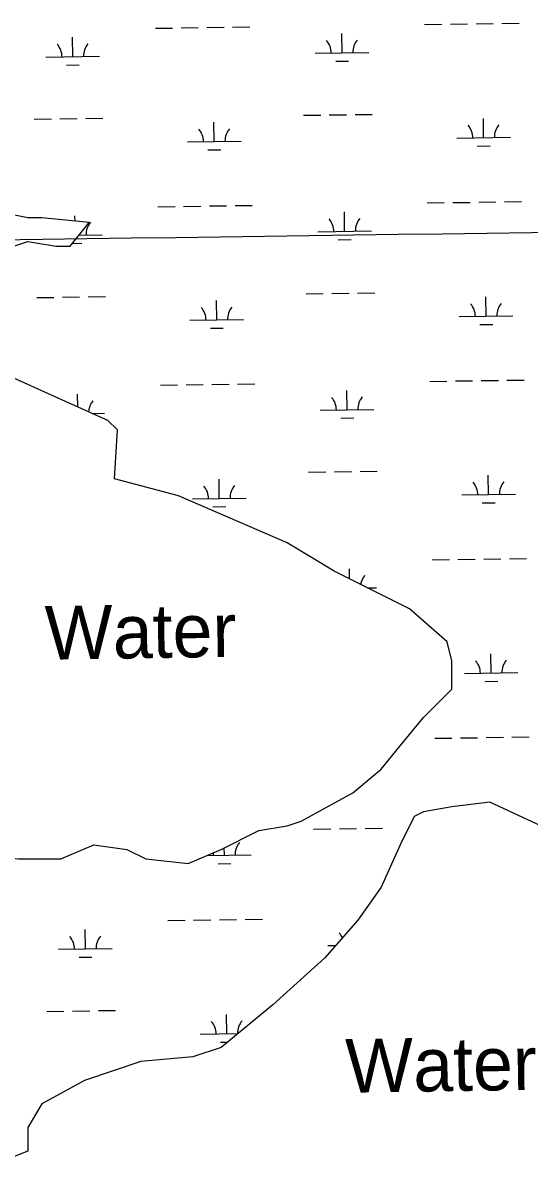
# Model space of a CAD drawing. Extents: x 3775218 to 3813389, y 343470 to 369318.
# Drawn here: x 3783560 to 3784504, y 353257 to 355414 of the extents above; entities that cross this region are included whole.
import ezdxf

# ---------------------------------------------------------------- set-up
doc = ezdxf.new("R2010")
doc.units = 0
for name, color, linetype in [('V-GRID-MAJR', 7, 'Continuous'), ('V-RIVR-IDEN', 7, 'Continuous'), ('V-TOPO-SHOR', 7, 'Continuous'), ('V-WETL-SWMP', 7, 'Continuous')]:
    doc.layers.add(name, color=color, linetype=linetype)

msp = doc.modelspace()

# ---------------------------------------------------------------- linework, layer by layer
at = {"layer": 'V-GRID-MAJR'}
msp.add_spline([(3779369.4, 354952.8), (3784672.7, 355025.7), (3789975.9, 355099.3), (3795279.1, 355173.8), (3800582.3, 355249), (3805885.5, 355325), (3811188.7, 355401.7)], degree=3, dxfattribs=at)
at = {"layer": 'V-TOPO-SHOR'}
for points in [[(3783542.1, 354998.2), (3783568.5, 355006.9), (3783621.1, 354998.2), (3783647.5, 354998.2), (3783682.6, 355042.1), (3783594.8, 355050.9), (3783568.5, 355050.9), (3783524.6, 355059.7)], [(3783730.2, 354564), (3783735.3, 354655.5), (3783717.7, 354673.1), (3783638.7, 354708.2), (3783542.1, 354752.1)], [(3784051.4, 353917.4), (3784077.7, 353926.2), (3784174.3, 353978.9), (3784227, 354022.8), (3784262.1, 354066.8), (3784306, 354119.5), (3784358.7, 354172.2), (3784358.7, 354224.9), (3784349.9, 354260.1), (3784279.7, 354321.6), (3784139.2, 354391.9), (3784051.4, 354444.6), (3783849.4, 354532.5), (3783730.2, 354564)], [(3783238.3, 354182.7), (3783243.6, 354172.2), (3783278.7, 354154.6), (3783252.4, 354075.5), (3783199.7, 354014), (3783199.7, 353970.1), (3783226, 353926.2), (3783287.5, 353908.6), (3783357.7, 353891), (3783410.4, 353864.7), (3783471.9, 353864.7), (3783550.9, 353855.9), (3783629.9, 353855.9), (3783691.4, 353882.2), (3783752.9, 353873.5), (3783788, 353855.9), (3783867, 353847.1), (3783928.5, 353873.5), (3783998.7, 353908.6), (3784051.4, 353917.4)], [(3784543.1, 353908.6), (3784429, 353961.3), (3784358.7, 353952.5), (3784306, 353943.7), (3784288.5, 353935), (3784262.1, 353882.2), (3784227, 353803.2), (3784183.1, 353741.7), (3784121.6, 353671.4), (3784025.1, 353583.5), (3783928.5, 353504.4), (3783875.8, 353486.8), (3783779.2, 353478.1), (3783673.8, 353442.9), (3783594.8, 353399), (3783568.5, 353355), (3783568.5, 353311.1)], [(3783568.5, 353311.1), (3783524.6, 353293.5), (3783463.1, 353293.5), (3783366.5, 353311.1), (3783322.6, 353267.2), (3783234.8, 353196.9)]]:
    msp.add_lwpolyline(points, dxfattribs=at)
at = {"layer": 'V-WETL-SWMP'}
for p, q in [((3783806, 355404.1), (3783838, 355404.5)), ((3783854, 355404.8), (3783886, 355405.2)), ((3783902, 355405.4), (3783934, 355405.9)), ((3783950, 355406.1), (3783982, 355406.6)), ((3784307.8, 355411.2), (3784339.8, 355411.6)), ((3784355.8, 355411.8), (3784387.8, 355412.3)), ((3784403.8, 355412.5), (3784435.8, 355413)), ((3784451.8, 355413.2), (3784483.8, 355413.6)), ((3783652.1, 355351.2), (3783651.6, 355387.2)), ((3784154, 355358.2), (3784153.5, 355394.2)), ((3783602.1, 355350.5), (3783702.1, 355351.9)), ((3784104, 355357.5), (3784204, 355358.9)), ((3784142.2, 355342.6), (3784166.2, 355343)), ((3783640.3, 355335.6), (3783664.3, 355335.9)), ((3783580.3, 355234.7), (3783612.3, 355235.2)), ((3783628.3, 355235.4), (3783660.3, 355235.8)), ((3783676.3, 355236.1), (3783708.3, 355236.5)), ((3784082.2, 355241.8), (3784114.2, 355242.2)), ((3784130.2, 355242.5), (3784162.2, 355242.9)), ((3784178.2, 355243.1), (3784210.2, 355243.6)), ((3784417.7, 355200.1), (3784417.2, 355236.1)), ((3783915.8, 355193), (3783915.3, 355229)), ((3783865.8, 355192.3), (3783965.8, 355193.7)), ((3784367.7, 355199.4), (3784467.7, 355200.8)), ((3783904, 355177.4), (3783928, 355177.7)), ((3784405.9, 355184.5), (3784429.9, 355184.8)), ((3784456.5, 355080.6), (3784488.5, 355081)), ((3783810.7, 355071.4), (3783842.7, 355071.9)), ((3783858.7, 355072.1), (3783890.7, 355072.6)), ((3783906.7, 355072.8), (3783938.7, 355073.2)), ((3783954.7, 355073.5), (3783986.7, 355073.9)), ((3784158.7, 355025.6), (3784158.2, 355061.6)), ((3784312.5, 355078.5), (3784344.5, 355079)), ((3784360.5, 355079.2), (3784392.5, 355079.6)), ((3784408.5, 355079.9), (3784440.5, 355080.3)), ((3783656.4, 355044.7), (3783656.3, 355054.5)), ((3783663.8, 355018.6), (3783706.8, 355019.2)), ((3784108.7, 355024.9), (3784208.7, 355026.3)), ((3783651.4, 355003), (3783669, 355003.3)), ((3784146.9, 355010), (3784170.9, 355010.3)), ((3784086.9, 354909.1), (3784118.9, 354909.6)), ((3784134.9, 354909.8), (3784166.9, 354910.3)), ((3784182.9, 354910.5), (3784214.9, 354911)), ((3783585, 354902.1), (3783617, 354902.5)), ((3783633, 354902.7), (3783665, 354903.2)), ((3783681, 354903.4), (3783713, 354903.9)), ((3783920.5, 354860.4), (3783920, 354896.4)), ((3784422.4, 354867.4), (3784421.9, 354903.4)), ((3784372.4, 354866.7), (3784472.4, 354868.1)), ((3783870.5, 354859.7), (3783970.5, 354861.1)), ((3783908.7, 354844.8), (3783932.7, 354845.1)), ((3784410.6, 354851.8), (3784434.6, 354852.2)), ((3783815.4, 354738.8), (3783847.4, 354739.2)), ((3783863.4, 354739.5), (3783895.4, 354739.9)), ((3783911.4, 354740.2), (3783943.4, 354740.6)), ((3783959.3, 354740.8), (3783991.3, 354741.3)), ((3784317.2, 354745.9), (3784349.2, 354746.3)), ((3784365.2, 354746.6), (3784397.2, 354747)), ((3784413.2, 354747.2), (3784445.2, 354747.7)), ((3784461.2, 354747.9), (3784493.2, 354748.4)), ((3783661.3, 354698.1), (3783661, 354721.9)), ((3784163.4, 354693), (3784162.9, 354729)), ((3784113.4, 354692.3), (3784213.4, 354693.7)), ((3783688, 354686.3), (3783711.5, 354686.6)), ((3784151.6, 354677.4), (3784175.6, 354677.7)), ((3783925.2, 354527.7), (3783924.7, 354563.7)), ((3784091.6, 354576.5), (3784123.6, 354577)), ((3784139.6, 354577.2), (3784171.6, 354577.6)), ((3784187.6, 354577.9), (3784219.6, 354578.3)), ((3784427.1, 354534.8), (3784426.5, 354570.8)), ((3783875.2, 354527), (3783975.2, 354528.4)), ((3784377.1, 354534.1), (3784477, 354535.5)), ((3783913.4, 354512.1), (3783937.4, 354512.5)), ((3784415.3, 354519.2), (3784439.3, 354519.5)), ((3784321.9, 354413.2), (3784353.9, 354413.7)), ((3784369.9, 354413.9), (3784401.9, 354414.4)), ((3784417.9, 354414.6), (3784449.9, 354415)), ((3784465.9, 354415.3), (3784497.9, 354415.7)), ((3784167.8, 354377.6), (3784167.5, 354396.3)), ((3784201.3, 354360.8), (3784218, 354361)), ((3784431.7, 354202.2), (3784431.2, 354238.2)), ((3784381.8, 354201.5), (3784481.7, 354202.9)), ((3784420, 354186.6), (3784444, 354186.9)), ((3784326.6, 354080.6), (3784358.6, 354081)), ((3784374.6, 354081.3), (3784406.6, 354081.7)), ((3784422.6, 354081.9), (3784454.6, 354082.4)), ((3784470.6, 354082.6), (3784502.6, 354083.1)), ((3784101, 353911.2), (3784133, 353911.7)), ((3784149, 353911.9), (3784181, 353912.3)), ((3784197, 353912.6), (3784229, 353913)), ((3783934.6, 353862.4), (3783934.4, 353876.4)), ((3783901.7, 353862), (3783984.6, 353863.1)), ((3783922.8, 353846.8), (3783946.8, 353847.2)), ((3783675.6, 353688), (3783675.1, 353724)), ((3783829.4, 353740.9), (3783861.4, 353741.3)), ((3783877.4, 353741.5), (3783909.4, 353742)), ((3783925.4, 353742.2), (3783957.4, 353742.7)), ((3783973.4, 353742.9), (3784005.4, 353743.4)), ((3783625.6, 353687.2), (3783725.6, 353688.7)), ((3784127.4, 353694.3), (3784141.9, 353694.5)), ((3783663.8, 353672.4), (3783687.8, 353672.7)), ((3783603.8, 353571.5), (3783635.8, 353571.9)), ((3783651.8, 353572.2), (3783683.8, 353572.6)), ((3783699.8, 353572.9), (3783731.8, 353573.3)), ((3783939.3, 353529.8), (3783938.8, 353565.8)), ((3783889.3, 353529.1), (3783959.8, 353530.1)), ((3783927.5, 353514.2), (3783940.6, 353514.4))]:
    msp.add_line(p, q, dxfattribs=at)
for points in [[(3783542.1, 354998.2), (3783568.5, 355006.9), (3783621.1, 354998.2), (3783647.5, 354998.2), (3783682.6, 355042.1), (3783594.8, 355050.9), (3783568.5, 355050.9), (3783524.6, 355059.7)], [(3783730.2, 354564), (3783735.3, 354655.5), (3783717.7, 354673.1), (3783638.7, 354708.2), (3783542.1, 354752.1)], [(3784051.4, 353917.4), (3784077.7, 353926.2), (3784174.3, 353978.9), (3784227, 354022.8), (3784262.1, 354066.8), (3784306, 354119.5), (3784358.7, 354172.2), (3784358.7, 354224.9), (3784349.9, 354260.1), (3784279.7, 354321.6), (3784139.2, 354391.9), (3784051.4, 354444.6), (3783849.4, 354532.5), (3783730.2, 354564)], [(3784543.1, 353908.6), (3784429, 353961.3), (3784358.7, 353952.5), (3784306, 353943.7), (3784288.5, 353935), (3784262.1, 353882.2), (3784227, 353803.2), (3784183.1, 353741.7), (3784121.6, 353671.4), (3784025.1, 353583.5), (3783928.5, 353504.4), (3783875.8, 353486.8), (3783779.2, 353478.1), (3783673.8, 353442.9), (3783594.8, 353399), (3783568.5, 353355), (3783568.5, 353311.1), (3783524.6, 353293.5), (3783463.1, 353293.5), (3783366.5, 353311.1), (3783322.6, 353267.2), (3783234.8, 353196.9)], [(3783550.9, 353855.9), (3783629.9, 353855.9), (3783691.4, 353882.2), (3783752.9, 353873.5), (3783788, 353855.9), (3783867, 353847.1), (3783928.5, 353873.5), (3783998.7, 353908.6), (3784051.4, 353917.4)]]:
    msp.add_lwpolyline(points, dxfattribs=at)
for centre, start, end in [((3783596.9, 355350.9), 0.0365, 41.5802), ((3783707.3, 355352.4), 140.0365, 181.5802), ((3784098.7, 355357.9), 0.0365, 41.5802), ((3784209.2, 355359.5), 140.0365, 181.5802), ((3783860.6, 355192.7), 0.0365, 41.5802), ((3783971, 355194.3), 140.0365, 181.5802), ((3784362.4, 355199.8), 0.0365, 41.5802), ((3784472.9, 355201.3), 140.0365, 181.5802), ((3783712, 355019.8), 140.0365, 181.5802), ((3784103.4, 355025.3), 0.0365, 41.5802), ((3784213.9, 355026.9), 140.0365, 181.5802), ((3784367.1, 354867.1), 0.0365, 41.5802), ((3784477.6, 354868.7), 140.0365, 181.5802), ((3783865.3, 354860.1), 0.0365, 41.5802), ((3783975.7, 354861.6), 140.0365, 181.5802), ((3784108.1, 354692.7), 0.0365, 41.5802), ((3784218.6, 354694.2), 140.0365, 181.5802), ((3783716.7, 354687.1), 140.0365, 176.7267), ((3783870, 354527.4), 0.0365, 41.5802), ((3783980.4, 354529), 140.0365, 181.5802), ((3784371.8, 354534.5), 0.0365, 41.5802), ((3784482.3, 354536.1), 140.0365, 181.5802), ((3784223.3, 354361.6), 140.0365, 170.797), ((3784376.5, 354201.9), 0.0365, 41.5802), ((3784487, 354203.4), 140.0365, 181.5802), ((3783989.8, 353863.7), 140.0365, 181.5802), ((3783879.3, 353862.1), 0.0365, 8.4873), ((3783620.3, 353687.6), 0.0365, 41.5802), ((3783730.8, 353689.2), 140.0365, 181.5802), ((3784122.2, 353694.7), 23.7091, 41.5802), ((3783884, 353529.5), 0.0365, 41.5802), ((3783994.5, 353531.1), 140.0365, 181.5802)]:
    msp.add_arc(centre, 35.2, start, end, dxfattribs=at)

# ---------------------------------------------------------------- texts
at = {"layer": 'V-RIVR-IDEN'}
for p in [(3783601.1, 354226.9), (3784160.9, 353419.7)]:
    msp.add_text('Water', height=100, rotation=0.9392, dxfattribs=at).set_placement(p)

doc.saveas('drawing.dxf')
